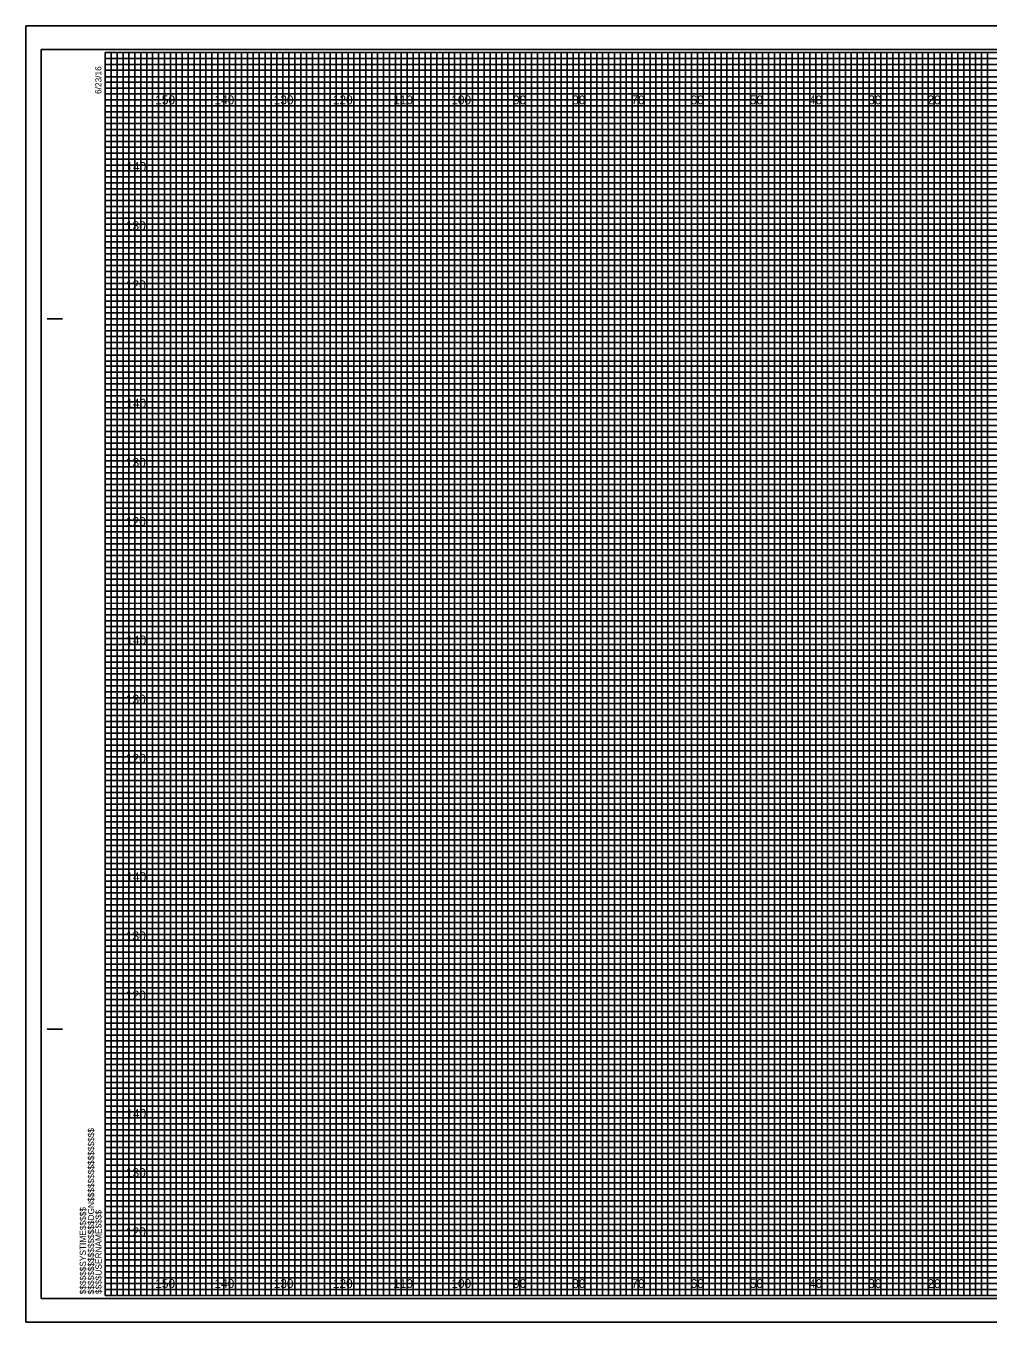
# Model space of a CAD drawing. Extents: x -13 to 323, y -5 to 874.
# Drawn here: x -13.4 to 149.1, y -4.5 to 214.5 of the extents above; entities that cross this region are included whole.
import ezdxf

# ---------------------------------------------------------------- set-up
doc = ezdxf.new("R2010")
doc.units = 0
for name, color, linetype in [('Exist Cross Section Cell', 7, 'Continuous'), ('Exist XS Center Line Elevation Label', 7, 'Continuous'), ('Exist XS Ground Line', 7, 'Continuous'), ('Prop CMT Pvmt Course 1', 7, 'Continuous'), ('Prop CMT Pvmt Course 3', 7, 'Continuous'), ('Prop CMT Pvmt Surface', 7, 'Continuous'), ('Prop CMT Pvmt Surface Shoulder', 7, 'Continuous'), ('Prop CMT Shld Paved Course 1', 7, 'Continuous'), ('Prop CMT Shld Paved Course 2', 7, 'Continuous'), ('Prop CMT Shld Paved Course 3', 7, 'Continuous'), ('Prop CMT Subgrade Earthwork', 7, 'Continuous')]:
    doc.layers.add(name, color=color, linetype=linetype)

msp = doc.modelspace()

# ---------------------------------------------------------------- linework, layer by layer
at = {"layer": 'Exist XS Center Line Elevation Label'}
for points in [[(0, 210), (5, 210), (5, 0), (15, 0), (15, 210), (25, 210), (25, 0), (35, 0), (35, 210), (45, 210), (45, 0), (55, 0), (55, 210), (65, 210), (65, 0), (75, 0), (75, 210), (85, 210), (85, 0), (95, 0), (95, 210), (105, 210), (105, 0), (115, 0), (115, 210), (125, 210), (125, 0), (135, 0), (135, 210), (145, 210), (145, 0), (155, 0)], [(0, 205), (275, 205)], [(0, 185), (320, 185), (320, 195), (0, 195)], [(0, 165), (320, 165), (320, 175), (0, 175)], [(0, 145), (320, 145), (320, 155), (0, 155)], [(0, 125), (320, 125), (320, 135), (0, 135)], [(0, 105), (320, 105), (320, 115), (0, 115)], [(0, 85), (320, 85), (320, 95), (0, 95)], [(0, 65), (320, 65), (320, 75), (0, 75)], [(0, 45), (320, 45), (320, 55), (0, 55)], [(0, 25), (320, 25), (320, 35), (0, 35)], [(0, 5), (320, 5), (320, 15), (0, 15)]]:
    msp.add_lwpolyline(points, dxfattribs=at)
at = {"layer": 'Exist XS Ground Line'}
for p, q in [((10, 210), (0, 210)), ((10, 0), (10, 210)), ((30, 210), (20, 210)), ((20, 210), (20, 0)), ((30, 0), (30, 210)), ((50, 210), (40, 210)), ((40, 210), (40, 0)), ((50, 0), (50, 210)), ((70, 210), (60, 210)), ((60, 210), (60, 0)), ((70, 0), (70, 210)), ((90, 210), (80, 210)), ((80, 210), (80, 0)), ((90, 0), (90, 210)), ((110, 210), (100, 210)), ((100, 210), (100, 0)), ((110, 0), (110, 210)), ((130, 210), (120, 210)), ((120, 210), (120, 0)), ((130, 0), (130, 210)), ((150, 210), (140, 210)), ((140, 210), (140, 0)), ((20, 0), (10, 0)), ((40, 0), (30, 0)), ((60, 0), (50, 0)), ((80, 0), (70, 0)), ((100, 0), (90, 0)), ((120, 0), (110, 0)), ((140, 0), (130, 0))]:
    msp.add_line(p, q, dxfattribs=at)
for points in [[(0, 200), (320, 200), (320, 190), (0, 190)], [(0, 180), (320, 180), (320, 170), (0, 170)], [(0, 160), (320, 160), (320, 150), (0, 150)], [(0, 140), (320, 140), (320, 130), (0, 130)], [(0, 120), (320, 120), (320, 110), (0, 110)], [(0, 100), (320, 100), (320, 90), (0, 90)], [(0, 80), (320, 80), (320, 70), (0, 70)], [(0, 60), (320, 60), (320, 50), (0, 50)], [(0, 40), (320, 40), (320, 30), (0, 30)], [(0, 20), (320, 20), (320, 10), (0, 10)]]:
    msp.add_lwpolyline(points, dxfattribs=at)
at = {"layer": 'Prop CMT Pvmt Course 3'}
msp.add_lwpolyline([(-13.4, -4.5), (323.3, -4.5), (323.3, 214.5), (-13.4, 214.5)], close=True, dxfattribs=at)
at = {"layer": 'Prop CMT Pvmt Surface'}
for p, q in [((10, 0), (10, 210)), ((20, 0), (20, 210)), ((30, 0), (30, 210)), ((40, 0), (40, 210)), ((50, 0), (50, 210)), ((60, 0), (60, 210)), ((70, 0), (70, 210)), ((80, 0), (80, 210)), ((90, 0), (90, 210)), ((100, 0), (100, 210)), ((110, 0), (110, 210)), ((120, 0), (120, 210)), ((130, 0), (130, 210)), ((140, 0), (140, 210)), ((0, 200), (320, 200)), ((0, 190), (320, 190)), ((0, 180), (320, 180)), ((0, 170), (320, 170)), ((0, 160), (320, 160)), ((0, 150), (320, 150)), ((0, 140), (320, 140)), ((0, 130), (320, 130)), ((0, 120), (320, 120)), ((0, 110), (320, 110)), ((0, 100), (320, 100)), ((0, 90), (320, 90)), ((0, 80), (320, 80)), ((0, 70), (320, 70)), ((0, 60), (320, 60)), ((0, 50), (320, 50)), ((0, 40), (320, 40)), ((0, 30), (320, 30)), ((0, 20), (320, 20)), ((0, 10), (320, 10))]:
    msp.add_line(p, q, dxfattribs=at)
at = {"layer": 'Prop CMT Pvmt Surface Shoulder'}
for p, q in [((323.3, 214.5), (-13.4, 214.5)), ((-13.4, 214.5), (-13.4, -4.5)), ((-13.4, -4.5), (323.3, -4.5))]:
    msp.add_line(p, q, dxfattribs=at)
at = {"layer": 'Prop CMT Shld Paved Course 1'}
for p, q in [((0, 209), (260, 209)), ((260, 207.98), (0, 207.98)), ((0, 207.98), (0, 207)), ((0, 207), (260, 207)), ((260, 205.89), (0, 205.89)), ((0, 205.89), (0, 204)), ((0, 204), (320, 204))]:
    msp.add_line(p, q, dxfattribs=at)
for points in [[(0, 203), (270, 203), (320, 203), (320, 202), (0, 202)], [(0, 201), (320, 201), (320, 199), (0, 199)], [(0, 198), (320, 198), (320, 197), (0, 196.98)], [(0, 196), (320, 196), (320, 194), (0, 194)], [(0, 193), (320, 193), (320, 192), (0, 192)], [(0, 191), (320, 191), (320, 189), (0, 189)], [(0, 188), (320, 188), (320, 187), (0, 187)], [(0, 186), (320, 186), (320, 184), (0, 184)], [(0, 183), (320, 183), (320, 182), (0, 182)], [(0, 181), (320, 181), (320, 179), (0, 179)], [(0, 178), (320, 178), (320, 177), (0, 177)], [(0, 176), (320, 176), (320, 173.95), (320, 173), (320, 172), (0, 172)], [(0, 174), (320, 174), (320, 173), (0, 173)], [(0, 171), (320, 171), (320, 169), (0, 169.03)], [(0, 169.03), (320, 169), (320, 168), (0, 168)], [(0, 167), (320, 167), (320, 166), (0, 166)], [(0, 164), (320, 164), (320, 163), (0, 163)], [(0, 162), (320, 162), (320, 161), (0, 161)], [(-0.07, 158.89), (320, 158.89), (320, 157.88), (-0.07, 157.88)], [(0, 157), (320, 157), (320, 156), (0, 156)], [(0, 154), (320, 154), (320, 153), (0, 153)], [(0, 152), (320, 152), (320, 151), (0, 151)], [(0, 149), (320, 149), (320, 148), (0, 148)], [(0, 147), (320, 147), (320, 146), (0, 146)], [(0, 144), (320, 144), (320, 143), (0, 143)], [(0, 142), (320, 142), (320, 141), (0, 141)], [(0, 139), (320, 139), (319.99, 137.98), (0, 138)], [(0, 137), (320, 137), (320, 136), (0, 136)], [(0, 134), (320, 134), (320, 133), (0, 133)], [(0, 132), (320, 132), (320, 131), (0, 131)], [(0, 129), (320, 129), (320, 128), (0, 128)], [(0, 127), (320, 127), (320, 126), (0, 126)], [(0, 124), (320, 124), (320, 123), (0, 123)], [(0, 122), (320, 122), (320, 121), (0, 121)], [(0, 119), (320, 119), (320, 118), (0, 118)], [(0, 116.99), (320.07, 116.91), (320, 116), (0, 116)], [(0, 114), (320, 114), (320, 113), (0, 113)], [(0, 112), (320, 112), (320, 111), (0, 111)], [(0, 109), (320, 109), (320, 108), (0, 108)], [(0, 107), (320, 107), (320, 106), (0, 106)], [(0, 104), (320, 104), (320, 103), (0, 103)], [(0, 102), (320, 102), (320, 101), (0, 101)], [(0, 99), (320, 99), (320, 98), (0, 98)], [(0, 97), (320, 97), (320, 96), (0, 96)], [(0, 94), (320, 94), (320, 93), (0, 93)], [(0, 92), (320, 92), (320, 91), (0, 91)], [(0, 89), (320, 89), (320, 88), (0, 88)], [(0, 87), (320, 87), (320, 86), (0, 86)], [(0, 84), (320, 84), (320, 83), (0, 83)], [(0, 82), (320, 82), (320, 81), (0, 81)], [(0, 79), (320, 79), (319.99, 77.98), (0, 78)], [(0, 77), (320, 77), (320, 76), (0, 76)], [(0, 74), (320, 74), (320, 73), (0, 73)], [(0, 72), (320, 72), (320, 71), (0, 71)], [(0, 69), (320, 69), (320, 68), (0, 68)], [(0, 67), (320, 67), (320, 66), (0, 66)], [(0, 64), (320, 64), (320, 63), (0, 63)], [(0, 62), (320, 62), (320, 61), (0, 61)], [(0, 59), (320, 59), (320, 58), (0, 58)], [(0, 56.99), (320.07, 56.91), (320, 56), (0, 56)], [(0, 54), (320, 54), (320, 53), (0, 53)], [(0, 52), (320, 52), (320, 51), (0, 51)], [(0, 49), (320, 49), (320, 48), (0, 48)], [(0, 47), (320, 47), (320, 46), (0, 46)], [(0, 44), (320, 44), (320, 43), (0, 43)], [(0, 42), (320, 42), (320, 41), (0, 41)], [(0, 39), (320, 39), (320, 38), (0, 38)], [(0, 37), (320, 37), (320, 36), (0, 36)], [(0, 34), (320, 34), (320, 33), (0, 33)], [(0, 32), (320, 32), (320, 31), (0, 31)], [(0, 29), (320, 29), (320, 28), (0, 28)], [(0, 27), (320, 27), (320, 26), (0, 26)], [(0, 24), (320, 24), (320, 23), (0, 23)], [(0, 22), (320, 22), (320, 21), (0, 21)], [(0, 19), (320, 19), (320, 18), (0, 18)], [(0, 17), (320, 17), (320, 16), (0, 16)], [(0, 14), (320, 14), (320, 13), (0, 13)], [(0, 12), (320, 12), (320, 11), (0, 11)], [(0, 9), (320, 9), (320, 8), (0, 8)], [(0, 7), (320, 7), (320, 6), (0, 6)], [(0, 4), (320, 4), (320, 3), (0, 3)], [(0, 2), (320, 2), (320, 1), (0, 1)]]:
    msp.add_lwpolyline(points, dxfattribs=at)
at = {"layer": 'Prop CMT Shld Paved Course 2'}
for p, q in [((-9.8, 165), (-7.3, 165)), ((-9.7, 165), (-7.2, 165)), ((-9.8, 45), (-7.3, 45)), ((-9.7, 45), (-7.2, 45)), ((0, 0), (0, 0)), ((0, 0), (0, 0)), ((0, 0), (0, 0)), ((0, 0), (0, 0)), ((0, 0), (0, 0)), ((0, 0), (0, 0)), ((0, 0), (0, 0))]:
    msp.add_line(p, q, dxfattribs=at)
msp.add_lwpolyline([(320, 210), (0, 210), (0, 0), (320, 0)], close=True, dxfattribs=at)
at = {"layer": 'Prop CMT Shld Paved Course 3'}
for points in [[(0, 0), (1, 0), (1, 210), (2, 210), (2, 0)], [(2, 0), (3, 0), (3, 210), (4, 210), (4, 0)], [(5, 0), (6, 0), (6, 210), (7, 210), (7, 0)], [(7, 0), (8, 0), (8, 210), (9, 210), (9, 0)], [(10, 0), (11, 0), (11, 210), (12, 210), (12, 0)], [(12, 0), (13, 0), (13, 210), (14, 210), (14, 0)], [(15, 0), (16, 0), (16, 210), (17, 210), (17, 0)], [(17, 0), (18, 0), (18, 210), (19, 210), (19, 0)], [(20, 0), (21, 0), (21, 210), (22, 210), (22, 0)], [(22, 0), (23, 0), (23, 210), (24, 210), (24, 0)], [(25, 0), (26, 0), (26, 210), (27, 210), (27, 0)], [(27, 0), (28, 0), (28, 210), (29, 210), (29, 0)], [(30, 0), (31, 0), (31, 210), (32, 210), (32, 0)], [(32, 0), (33, 0), (33, 210), (34, 210), (34, 0)], [(35, 0), (36, 0), (36, 210), (37, 210), (37, 0)], [(37, 0), (38, 0), (38, 210), (39, 210), (39, 0)], [(40, 0), (41, 0), (41, 210), (42, 210), (42, 0)], [(42, 0), (43, 0), (43, 210), (44, 210), (44, 0)], [(45, 0), (46, 0), (46, 210), (47, 210), (47, 0)], [(47, 0), (48, 0), (48, 210), (49, 210), (49, 0)], [(50, 0), (51, 0), (51, 210), (52, 210), (52, 0)], [(52, 0), (53, 0), (53, 210), (54, 210), (54, 0)], [(55, 0), (56, 0), (56, 210), (57, 210), (57, 0)], [(57, 0), (58, 0), (58, 210), (59, 210), (59, 0)], [(60, 0), (61, 0), (61, 210), (62, 210), (62, 0)], [(62, 0), (63, 0), (63, 210), (64, 210), (64, 0)], [(65, 0), (66, 0), (66, 210), (67, 210), (67, 0)], [(67, 0), (68, 0), (68, 210), (69, 210), (69, 0)], [(70, 0), (71, 0), (71, 210), (72, 210), (72, 0)], [(72, 0), (73, 0), (73, 210), (74, 210), (74, 0)], [(75, 0), (76, 0), (76, 210), (77, 210), (77, 0)], [(77, 0), (78, 0), (78, 210), (79, 210), (79, 0)], [(80, 0), (81, 0), (81, 210), (82, 210), (82, 0)], [(82, 0), (83, 0), (83, 210), (84, 210), (84, 0)], [(85, 0), (86, 0), (86, 210), (87, 210), (87, 0)], [(87, 0), (88, 0), (88, 210), (89, 210), (89, 0)], [(90, 0), (91, 0), (91, 210), (92, 210), (92, 0)], [(92, 0), (93, 0), (93, 210), (94, 210), (94, 0)], [(95, 0), (96, 0), (96, 210), (97, 210), (97, 0)], [(97, 0), (98, 0), (98, 210), (99, 210), (99, 0)], [(100, 0), (101, 0), (101, 210), (102, 210), (102, 0)], [(102, 0), (103, 0), (103, 210), (104, 210), (104, 0)], [(105, 0), (106, 0), (106, 210), (107, 210), (107, 0)], [(107, 0), (108, 0), (108, 210), (109, 210), (109, 0)], [(110, 0), (111, 0), (111, 210), (112, 210), (112, 0)], [(112, 0), (113, 0), (113, 210), (114, 210), (114, 0)], [(115, 0), (116, 0), (116, 210), (117, 210), (117, 0)], [(117, 0), (118, 0), (118, 210), (119, 210), (119, 0)], [(120, 0), (121, 0), (121, 210), (122, 210), (122, 0)], [(122, 0), (123, 0), (123, 210), (124, 210), (124, 0)], [(125, 0), (126, 0), (126, 210), (127, 210), (127, 0)], [(127, 0), (128, 0), (128, 210), (129, 210), (129, 0)], [(130, 0), (131, 0), (131, 210), (132, 210), (132, 0)], [(132, 0), (133, 0), (133, 210), (134, 210), (134, 0)], [(135, 0), (136, 0), (136, 210), (137, 210), (137, 0)], [(137, 0), (138, 0), (138, 210), (139, 210), (139, 0)], [(140, 0), (141, 0), (141, 210), (142, 210), (142, 0)], [(142, 0), (143, 0), (143, 210), (144, 210), (144, 0)], [(145, 0), (146, 0), (146, 210), (147, 210), (147, 0)], [(147, 0), (148, 0), (148, 210), (149, 210), (149, 0)]]:
    msp.add_lwpolyline(points, dxfattribs=at)
at = {"layer": 'Prop CMT Subgrade Earthwork'}
msp.add_lwpolyline([(-10.8, -0.5), (322.4, -0.5), (322.4, 210.5), (-10.8, 210.5)], close=True, dxfattribs=at)

# ---------------------------------------------------------------- texts
at = {"layer": 'Exist Cross Section Cell'}
for s, p in [('150', (8.44, 201.25)), ('140', (18.44, 201.25)), ('130', (28.44, 201.25)), ('120', (38.44, 201.25)), ('110', (48.62, 201.25)), ('100', (58.44, 201.25)), ('90', (68.86, 201.25)), ('80', (78.86, 201.25)), ('70', (88.86, 201.25)), ('60', (98.86, 201.25)), ('50', (108.86, 201.25)), ('40', (118.86, 201.25)), ('30', (128.86, 201.25)), ('20', (138.86, 201.25)), ('150', (8.44, 1.25)), ('140', (18.44, 1.25)), ('130', (28.44, 1.25)), ('120', (38.44, 1.25)), ('110', (48.62, 1.25)), ('100', (58.44, 1.25)), ('90', (68.86, 1.25)), ('80', (78.86, 1.25)), ('70', (88.86, 1.25)), ('60', (98.86, 1.25)), ('50', (108.86, 1.25)), ('40', (118.86, 1.25)), ('30', (128.86, 1.25)), ('20', (138.86, 1.25))]:
    msp.add_text(s, height=1.5, dxfattribs=at).set_placement(p)
at = {"layer": 'Prop CMT Pvmt Course 1'}
for s, p in [('140', (3.57, 190)), ('130', (3.49, 180)), ('120', (3.5, 170)), ('140', (3.57, 150)), ('130', (3.49, 140)), ('120', (3.5, 130)), ('140', (3.57, 110)), ('130', (3.49, 100)), ('120', (3.5, 90)), ('140', (3.57, 70)), ('130', (3.49, 60)), ('120', (3.5, 50)), ('140', (3.57, 30)), ('130', (3.49, 20)), ('120', (3.5, 10))]:
    msp.add_text(s, height=1.5, dxfattribs=at).set_placement(p)
at = {"layer": 'Prop CMT Shld Paved Course 2'}
for s, p in [('6/23/16', (-0.65, 203)), ('$$$$$$$$$$$$$$$$DGN$$$$$$$$$$$$$$$$', (-1.88, 0.18)), ('$$$$$$SYSTIME$$$$$', (-3.26, 0.18)), ('$$$$USERNAME$$$$', (-0.62, 0.23))]:
    msp.add_text(s, height=1.05, rotation=90, dxfattribs=at).set_placement(p)

doc.saveas('drawing.dxf')
